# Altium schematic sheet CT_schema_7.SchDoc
size 365 x 335 mm
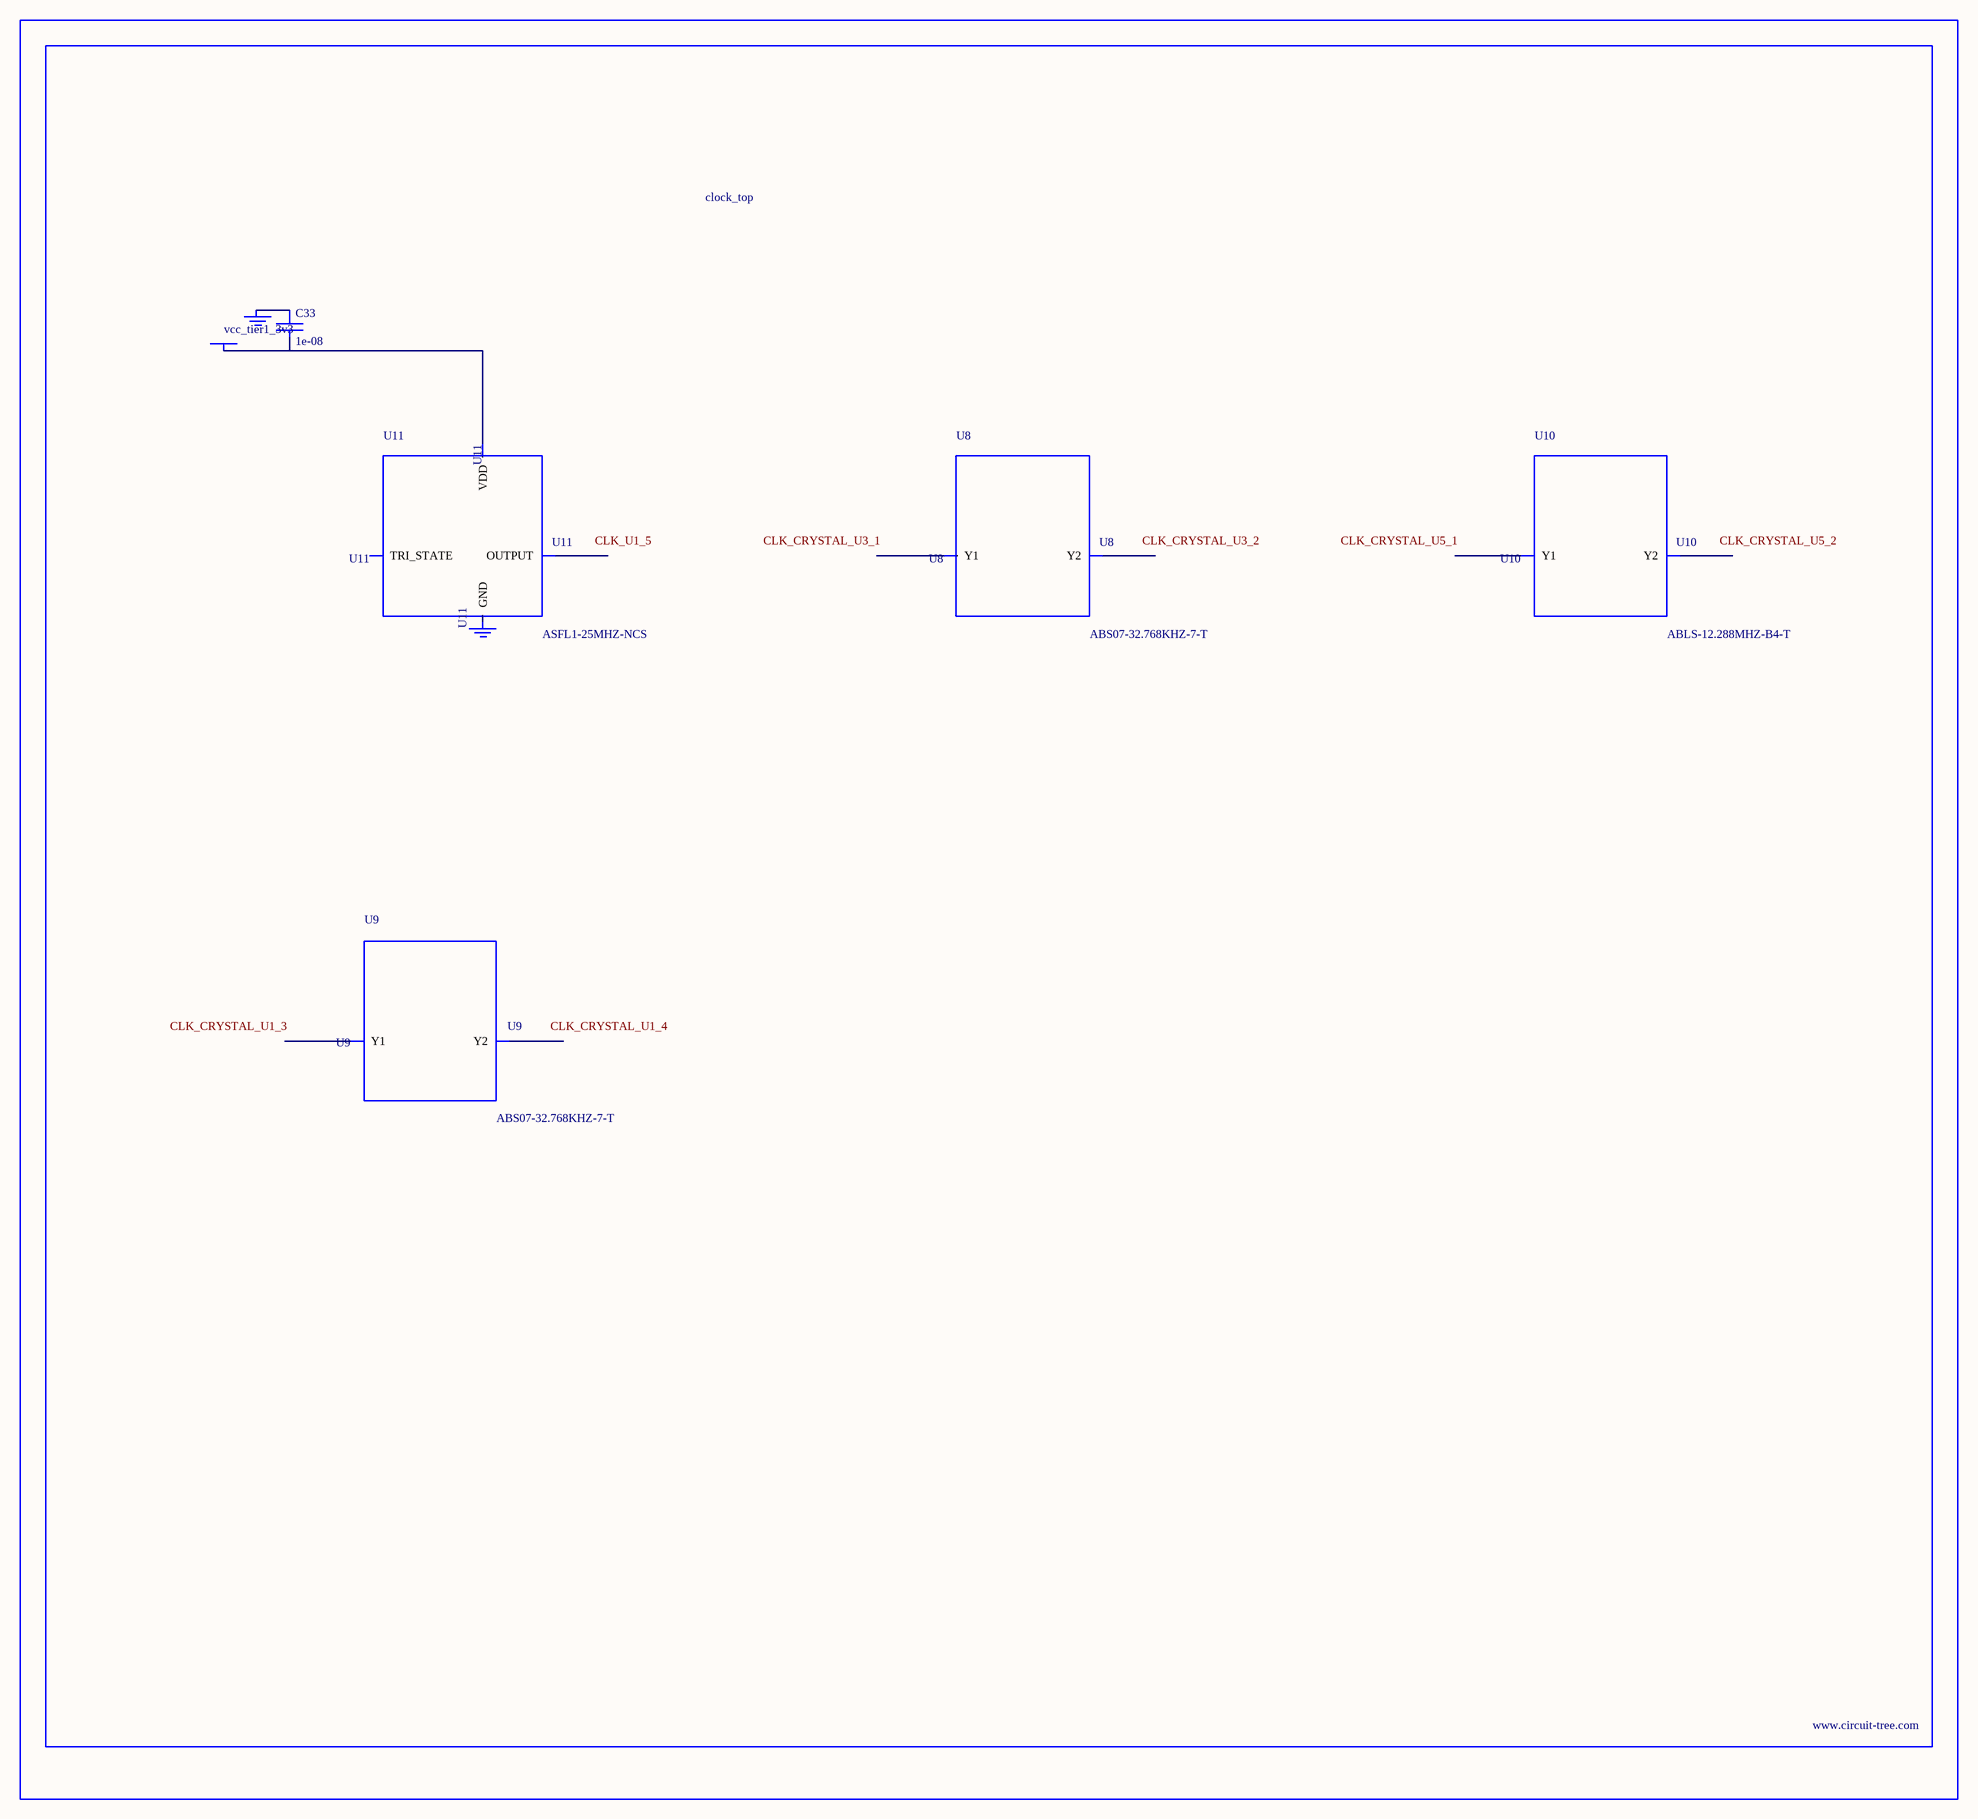
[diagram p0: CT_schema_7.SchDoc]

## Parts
BORDER6  (no value)
C33  1e-08  [C0402]
GND_INSTANCE_6_0  (no value)
GND_INSTANCE_6_1  (no value)
POWER_INSTANCE_6_0  vcc_tier1_3v3
U8  ABS07-32.768KHZ-7-T  [ABS07-32.768KHZ-7-T]
U9  ABS07-32.768KHZ-7-T  [ABS07-32.768KHZ-7-T]
U10  ABLS-12.288MHZ-B4-T  [ABLS-12.288MHZ-B4-T]
U11  ASFL1-25MHZ-NCS  [ASFL1]

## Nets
NetC33_1: C33.1 GND_INSTANCE_6_0.0(GND)
NetC33_2: C33.2 POWER_INSTANCE_6_0.0(PWR) U11.4(VDD)

Not connected (* = marked no-connect by the designer): GND_INSTANCE_6_1 0(GND); U8 1(Y1) 2(Y2); U9 1(Y1) 2(Y2); U10 1(Y1) 2(Y2); U11 1(TRI_STATE) 2(GND) 3(OUTPUT)

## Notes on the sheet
- Labels drawn without touching a wire or pin: CLK_CRYSTAL_U1_3, CLK_CRYSTAL_U1_4, CLK_CRYSTAL_U3_1, CLK_CRYSTAL_U3_2, CLK_CRYSTAL_U5_1, CLK_CRYSTAL_U5_2, CLK_U1_5

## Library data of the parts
BORDER6 = BORDER_PAGE6
C33 = C0402C103K3RAC
GND_INSTANCE_6_0 GND_INSTANCE_6_1 = GND
POWER_INSTANCE_6_0 = PWR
